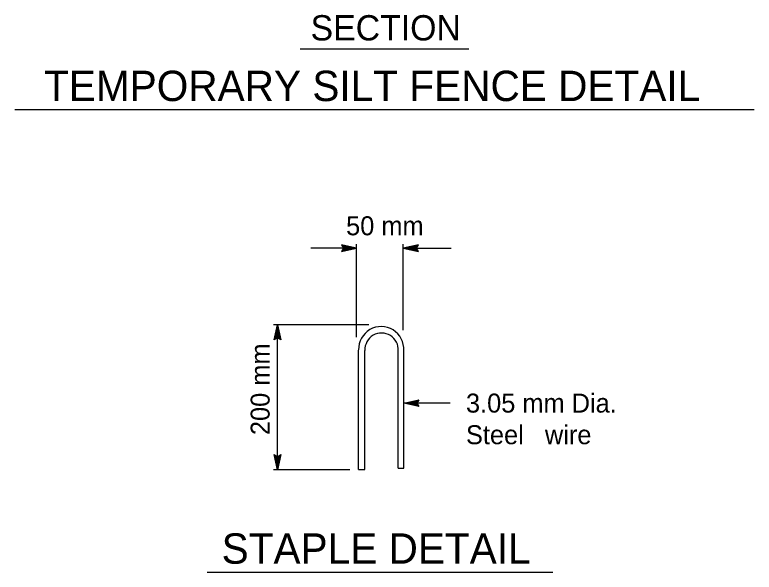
# Model space of a CAD drawing. Extents: x 6707406 to 6714471, y 1868570 to 1872341.
# Drawn here: x 6710113.5 to 6710394.1, y 1871525.7 to 1871737.2 of the extents above; entities that cross this region are included whole.
import ezdxf

# ---------------------------------------------------------------- set-up
doc = ezdxf.new("R2010")
doc.units = 0
for name, color, linetype in [('56 Stg 3 Anno', 7, 'Continuous'), ('57 Undefined', 7, 'Continuous'), ('60 Nongeo Data', 7, 'Continuous')]:
    doc.layers.add(name, color=color, linetype=linetype)

msp = doc.modelspace()

# ---------------------------------------------------------------- linework, layer by layer
at = {"layer": '56 Stg 3 Anno'}
for p, q in [((6710243.21, 1871648.67), (6710237.45, 1871649.94)), ((6710237.45, 1871649.94), (6710237.45, 1871649.94)), ((6710237.45, 1871649.94), (6710238.22, 1871648.67)), ((6710241.87, 1871648.67), (6710237.67, 1871649.6)), ((6710243.22, 1871614.9), (6710243.22, 1871650.11)), ((6710260.93, 1871617.52), (6710260.93, 1871650.11)), ((6710266.69, 1871649.95), (6710260.93, 1871648.67)), ((6710266.48, 1871649.61), (6710262.26, 1871648.67)), ((6710265.92, 1871648.67), (6710266.69, 1871649.95)), ((6710266.69, 1871649.95), (6710266.69, 1871649.95)), ((6710243.13, 1871648.67), (6710225.89, 1871648.67)), ((6710238.22, 1871648.67), (6710237.45, 1871647.38)), ((6710237.45, 1871647.38), (6710243.21, 1871648.67)), ((6710237.45, 1871647.38), (6710237.45, 1871647.38)), ((6710237.66, 1871647.72), (6710241.88, 1871648.67)), ((6710240.56, 1871648.67), (6710237.84, 1871649.27)), ((6710237.88, 1871648.07), (6710240.56, 1871648.67)), ((6710238.05, 1871648.4), (6710239.23, 1871648.66)), ((6710239.23, 1871648.66), (6710238.07, 1871648.92)), ((6710243.21, 1871648.67), (6710243.21, 1871648.67)), ((6710260.93, 1871648.67), (6710260.93, 1871648.67)), ((6710260.93, 1871648.67), (6710266.69, 1871647.39)), ((6710261.36, 1871648.67), (6710279.07, 1871648.67)), ((6710262.27, 1871648.66), (6710266.47, 1871647.74)), ((6710266.26, 1871649.27), (6710263.58, 1871648.67)), ((6710263.58, 1871648.67), (6710266.29, 1871648.07)), ((6710266.09, 1871648.93), (6710264.91, 1871648.67)), ((6710264.91, 1871648.67), (6710266.07, 1871648.41)), ((6710266.69, 1871647.39), (6710265.92, 1871648.67)), ((6710266.69, 1871647.39), (6710266.69, 1871647.39)), ((6710247.86, 1871619.57), (6710211.74, 1871619.57)), ((6710211.89, 1871613.81), (6710213.18, 1871619.57)), ((6710213.18, 1871564.52), (6710213.18, 1871619.57)), ((6710213.18, 1871619.57), (6710213.18, 1871619.57)), ((6710213.18, 1871619.57), (6710214.45, 1871613.81)), ((6710212.23, 1871614.02), (6710213.18, 1871618.25)), ((6710212.58, 1871614.25), (6710213.17, 1871616.92)), ((6710213.17, 1871616.92), (6710213.78, 1871614.21)), ((6710213.18, 1871618.24), (6710214.11, 1871614.04)), ((6710213.18, 1871614.58), (6710211.89, 1871613.81)), ((6710211.89, 1871613.81), (6710211.89, 1871613.81)), ((6710212.91, 1871614.42), (6710213.17, 1871615.6)), ((6710213.17, 1871615.6), (6710213.43, 1871614.44)), ((6710214.45, 1871613.81), (6710213.18, 1871614.58)), ((6710214.45, 1871613.81), (6710214.45, 1871613.81)), ((6710261.13, 1871589.84), (6710266.89, 1871591.12)), ((6710262.46, 1871589.85), (6710266.66, 1871590.77)), ((6710266.89, 1871591.12), (6710266.12, 1871589.84)), ((6710266.89, 1871591.12), (6710266.89, 1871591.12)), ((6710278.68, 1871589.84), (6710261.13, 1871589.84)), ((6710266.89, 1871588.56), (6710261.13, 1871589.84)), ((6710261.13, 1871589.84), (6710261.13, 1871589.84)), ((6710266.68, 1871588.9), (6710262.45, 1871589.84)), ((6710263.78, 1871589.84), (6710266.49, 1871590.44)), ((6710266.46, 1871589.24), (6710263.78, 1871589.84)), ((6710265.11, 1871589.84), (6710266.27, 1871590.1)), ((6710266.29, 1871589.58), (6710265.11, 1871589.84)), ((6710266.12, 1871589.84), (6710266.89, 1871588.56)), ((6710266.89, 1871588.56), (6710266.89, 1871588.56)), ((6710213.18, 1871564.52), (6710211.9, 1871570.28)), ((6710211.9, 1871570.28), (6710211.9, 1871570.28)), ((6710211.9, 1871570.28), (6710213.18, 1871569.51)), ((6710213.17, 1871565.85), (6710212.24, 1871570.05)), ((6710213.18, 1871567.17), (6710212.58, 1871569.88)), ((6710213.18, 1871568.49), (6710212.92, 1871569.66)), ((6710213.18, 1871569.51), (6710214.46, 1871570.28)), ((6710214.46, 1871570.28), (6710213.18, 1871564.52)), ((6710214.12, 1871570.07), (6710213.18, 1871565.84)), ((6710213.78, 1871569.84), (6710213.18, 1871567.17)), ((6710213.44, 1871569.67), (6710213.18, 1871568.49)), ((6710214.46, 1871570.28), (6710214.46, 1871570.28)), ((6710240.68, 1871564.52), (6710211.74, 1871564.52)), ((6710213.18, 1871564.52), (6710213.18, 1871564.52))]:
    msp.add_line(p, q, dxfattribs=at)
at = {"layer": '57 Undefined'}
for p, q in [((6710221.78, 1871724.22), (6710285.84, 1871724.22)), ((6710113.48, 1871701.22), (6710394.15, 1871701.22)), ((6710186.55, 1871525.68), (6710317.67, 1871525.68))]:
    msp.add_line(p, q, dxfattribs=at)
at = {"layer": '60 Nongeo Data'}
for p, q in [((6710244, 1871564.66), (6710244, 1871609.99)), ((6710246.36, 1871564.66), (6710246.36, 1871609.85)), ((6710259.04, 1871565.11), (6710259.04, 1871609.69)), ((6710261.13, 1871565.11), (6710261.13, 1871609.78)), ((6710244, 1871564.66), (6710246.36, 1871564.66)), ((6710259.04, 1871565.11), (6710261.13, 1871565.11))]:
    msp.add_line(p, q, dxfattribs=at)
for centre, major_axis in [((6710252.57, 1871610.3), (0, -8.58)), ((6710252.71, 1871610.08), (0, -6.35))]:
    msp.add_ellipse(centre, major_axis=major_axis, ratio=0.999991, start_param=1.510257, end_param=4.748244, dxfattribs=at)

# ---------------------------------------------------------------- texts
at = {"layer": '57 Undefined'}
for s, height, p in [('SECTION', 9.6, (6710225.75, 1871727.44)), ('TEMPORARY SILT FENCE DETAIL', 11.5197, (6710124.57, 1871704.44)), ('50 mm ', 7.2, (6710239.24, 1871653.52)), ('3.05 mm Dia.', 7.1998, (6710284.74, 1871586.24)), ('Steel   wire', 7.1998, (6710284.74, 1871574.24)), ('STAPLE DETAIL', 11.5197, (6710191.99, 1871528.9))]:
    msp.add_text(s, height=height, dxfattribs=at).set_placement(p)
msp.add_text('200 mm ', height=7.2, rotation=90, dxfattribs=at).set_placement((6710210.21, 1871577.7))

doc.saveas('drawing.dxf')
